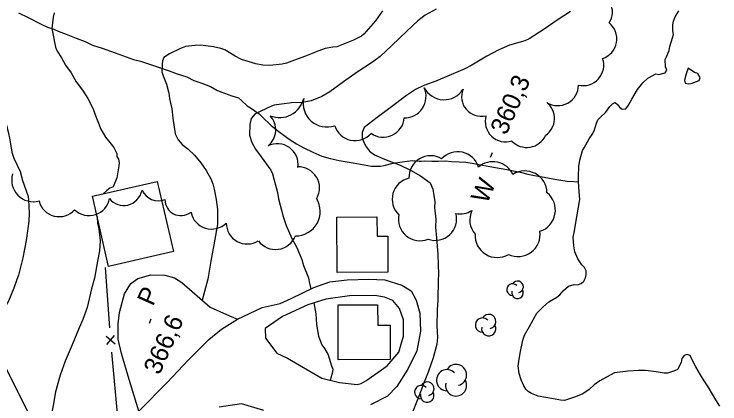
# Model space of a CAD drawing. Extents: x 287698 to 290158, y 5234163 to 5237182.
# Drawn here: x 288989.7 to 289106, y 5234678.1 to 5234742.3 of the extents above; entities that cross this region are included whole.
import ezdxf

# ---------------------------------------------------------------- set-up
doc = ezdxf.new("R2010")
doc.units = 0
for name, color, linetype in [('Niveau 1', 7, 'Continuous'), ('Niveau 19', 7, 'Continuous'), ('Niveau 2', 7, 'Continuous'), ('Niveau 3', 7, 'Continuous'), ('Niveau 31', 7, 'Continuous'), ('Niveau 37', 7, 'Continuous'), ('Niveau 4', 7, 'Continuous'), ('Niveau 44', 7, 'Continuous'), ('Niveau 52', 7, 'Continuous')]:
    doc.layers.add(name, color=color, linetype=linetype)

msp = doc.modelspace()

# ---------------------------------------------------------------- linework, layer by layer
at = {"layer": 'Niveau 1'}
for points in [[(288980.01, 5234742.77), (288979.81, 5234741.62), (288979.28, 5234738.63), (288979.42, 5234737.59), (288979.65, 5234737.06), (288980.74, 5234734.7), (288981.43, 5234733.68), (288982.27, 5234732.9), (288983.04, 5234731.98), (288984.94, 5234729.61), (288985.58, 5234728.54), (288986.45, 5234727.58), (288987.25, 5234726.58), (288987.91, 5234725.41), (288988.36, 5234724.15), (288988.68, 5234722.86), (288988.94, 5234721.55), (288989.28, 5234719.56), (288989.61, 5234718.55), (288990.18, 5234717.39), (288990.64, 5234716.36), (288990.95, 5234715.33), (288990.98, 5234715.04)], [(288990.98, 5234715.04), (288991.97, 5234712.23), (288992.01, 5234711.69), (288992.11, 5234709.46), (288992.06, 5234708.15), (288991.88, 5234706.55), (288991.62, 5234704.99), (288991.1, 5234702.12), (288990.39, 5234699.28), (288990.1, 5234698.54), (288989.6, 5234697.11), (288988.72, 5234694.99), (288987.99, 5234693.73), (288987.29, 5234692.27), (288986.15, 5234690.16), (288985.28, 5234688.81), (288984.18, 5234687.18)]]:
    msp.add_lwpolyline(points, dxfattribs=at)
at = {"layer": 'Niveau 19'}
for points in [[(289026.5, 5234692.01), (289030.59, 5234693.91), (289033.52, 5234694.59), (289035.37, 5234695.44), (289039.08, 5234697.25), (289041.74, 5234698.18), (289044.56, 5234698.49), (289048.15, 5234698.59), (289050.77, 5234698.47), (289053.6, 5234697.61), (289055.11, 5234696.69), (289055.97, 5234695.12), (289056.55, 5234693.01), (289056.66, 5234690.06), (289056.08, 5234686.77), (289054.57, 5234683.75), (289052.8, 5234680.94), (289051.21, 5234679.31), (289048.41, 5234677.91)], [(289047.68, 5234681.84), (289051.18, 5234684.33), (289053.1, 5234686.57), (289053.89, 5234689.19), (289053.85, 5234691.88), (289053.19, 5234693.76), (289052.1, 5234695.09), (289050.74, 5234695.64), (289049.12, 5234695.92), (289044.97, 5234695.86), (289041.08, 5234695.33), (289038.08, 5234694.35), (289033.93, 5234692.47), (289031.04, 5234690.46), (289031.11, 5234688.9), (289033, 5234686.4), (289034.75, 5234685.58), (289040.43, 5234682.3), (289043.3, 5234681.57), (289046.21, 5234681.24), (289046.91, 5234681.39), (289047.68, 5234681.84)], [(289010.22, 5234676.83), (289014.91, 5234681.58), (289018.41, 5234685.29), (289021.77, 5234688.66), (289023.87, 5234690.36), (289026.5, 5234692.01)], [(289030.84, 5234676.99), (289027.17, 5234678.06), (289023.48, 5234677.52)]]:
    msp.add_lwpolyline(points, dxfattribs=at)
at = {"layer": 'Niveau 2'}
for points in [[(289059.28, 5234743.09), (289057.43, 5234742.11), (289056.21, 5234741.2), (289054.46, 5234739.5), (289051.95, 5234737.09), (289050.01, 5234735.3), (289048.75, 5234734.38), (289046.22, 5234732.7), (289043.96, 5234731.12), (289041.74, 5234729.5), (289040.38, 5234728.71), (289038.67, 5234727.99), (289037.16, 5234727.74), (289035.38, 5234727.68), (289032.54, 5234727.3), (289032.11, 5234727.11), (289029.43, 5234725.87), (289028.74, 5234725.09), (289028.54, 5234724.07), (289028.47, 5234722.34), (289028.87, 5234721.13), (289029.47, 5234720.05), (289030.42, 5234718.79), (289032.02, 5234716.58), (289032.29, 5234715.98), (289033.07, 5234712.91), (289033.25, 5234711.82), (289034.02, 5234708.94), (289034.51, 5234707.47), (289035.43, 5234705.3), (289036.21, 5234703.93), (289037.11, 5234701.83), (289037.38, 5234700.87), (289038.2, 5234698.84), (289038.32, 5234698.16), (289038.59, 5234697.01)], [(288996.24, 5234742.47), (288996.11, 5234741.78), (288995.9, 5234739.89), (288996.03, 5234739.1), (288996.48, 5234736.84), (288996.78, 5234736.2), (288997.45, 5234735.09), (288998.11, 5234733.88), (288999.04, 5234732.59), (288999.9, 5234731.1), (289000.94, 5234729.74), (289001.83, 5234728.37), (289002.67, 5234726.69), (289002.99, 5234725.83), (289003.97, 5234723.32), (289004.73, 5234721.99), (289005.43, 5234721.13), (289006.11, 5234720.28), (289006.59, 5234719.32), (289006.6, 5234718.81), (289006.87, 5234718.36), (289006.99, 5234717.77), (289006.92, 5234717.27), (289006.57, 5234715.3), (289005.99, 5234713.82), (289005.44, 5234713.59), (289004.97, 5234713.23), (289004.35, 5234712.67)], [(289050.42, 5234742.81), (289049.24, 5234741.2), (289047.33, 5234738.97), (289046.93, 5234738.66), (289045.65, 5234737.98)], [(289081.44, 5234742.73), (289079.24, 5234741.29), (289077.05, 5234739.8), (289074.58, 5234738.19), (289073.88, 5234737.9), (289071.33, 5234737.15), (289069.47, 5234736.36), (289067.61, 5234735.36), (289065.13, 5234733.85), (289063.86, 5234733.19), (289061.79, 5234732.34), (289059.21, 5234731.25), (289057.2, 5234730.54), (289055.86, 5234729.86), (289054.38, 5234728.85), (289051.68, 5234726.84), (289049.55, 5234725.24), (289047.36, 5234723.6), (289047.04, 5234722.8), (289047.08, 5234721.81), (289047.59, 5234720.57), (289048.24, 5234719.69), (289049.11, 5234719.09), (289050.75, 5234718.4), (289053.31, 5234717.37), (289055.01, 5234716.58), (289056.67, 5234715.66), (289058.25, 5234714.46), (289058.7, 5234713.42), (289059.04, 5234711.35), (289059, 5234710.4), (289059.22, 5234708.5), (289059.17, 5234707.15), (289059.31, 5234705.42), (289059.56, 5234702.67), (289059.67, 5234699.4), (289059.58, 5234698.52), (289059.52, 5234695.13), (289059.41, 5234693.54), (289059.39, 5234690.92), (289059.48, 5234688.99), (289059.37, 5234687.88), (289058.77, 5234685.66), (289057.96, 5234683.26), (289057.27, 5234681.61), (289056.25, 5234678.88), (289055.18, 5234676.25)], [(289045.65, 5234737.98), (289042.89, 5234736.87), (289042.21, 5234736.81), (289040.96, 5234736.61), (289039.91, 5234736.22), (289037.7, 5234735.33), (289036.35, 5234734.88), (289034.6, 5234734.21), (289033.87, 5234734.06), (289031.83, 5234733.81), (289030.68, 5234733.87), (289029.5, 5234734.08), (289027.13, 5234734.78), (289026.13, 5234735.34), (289024.42, 5234736.37), (289023.76, 5234736.63), (289022.56, 5234736.87), (289020.42, 5234737.14), (289019.54, 5234737.13), (289017.9, 5234736.92), (289017.11, 5234736.59), (289015.3, 5234735.75), (289014.36, 5234735.16), (289014.15, 5234734.57), (289014.07, 5234734), (289014.02, 5234732.75), (289014.23, 5234732.1), (289014.76, 5234730.75), (289015.15, 5234729.26), (289015.27, 5234728.36), (289015.64, 5234726.65), (289015.85, 5234725.15), (289016.24, 5234722.57), (289016.72, 5234721.59), (289017.38, 5234720.82), (289018.28, 5234720.07), (289019.43, 5234719.02), (289020.46, 5234717.8), (289021.35, 5234716.53), (289022.12, 5234715.15), (289022.44, 5234714.3), (289022.65, 5234713.43), (289023, 5234711.71), (289023.22, 5234710.1), (289023.22, 5234709.29), (289023.17, 5234707.61), (289023.02, 5234706.75), (289022.58, 5234704.27), (289022.11, 5234701.59), (289021.58, 5234698.61), (289020.65, 5234695.15)], [(289003.33, 5234708.91), (289003.39, 5234707.79)], [(289003.39, 5234707.79), (289003.61, 5234706.89), (289003.83, 5234704.91), (289003.71, 5234703.27), (289003.43, 5234701.58), (289002.9, 5234698.79), (289002.4, 5234697.03), (289001.68, 5234693.96), (289001, 5234691.94), (289000.4, 5234690.57), (288999.21, 5234687.8), (288998.05, 5234685.08), (288997.24, 5234682.76), (288996.49, 5234680.02), (288996.08, 5234677.78), (288995.58, 5234675.3), (288994.99, 5234672.51), (288994.42, 5234669.37), (288994.37, 5234668.33), (288994.09, 5234665.85), (288993.76, 5234664.9), (288992.79, 5234663.25), (288991.58, 5234661.16)], [(289039.1, 5234694.68), (289039.41, 5234692.87), (289039.52, 5234691.16), (289039.86, 5234689.19), (289040.39, 5234687.76), (289040.83, 5234687.19), (289041.43, 5234686.16)], [(289041.43, 5234686.16), (289041.99, 5234684.33), (289042.2, 5234683.79), (289042.09, 5234683.08), (289041.76, 5234681.96)]]:
    msp.add_lwpolyline(points, dxfattribs=at)
at = {"layer": 'Niveau 3'}
for p, q in [((289068.24, 5234718.73), (289068.56, 5234719.46)), ((289011.96, 5234691.33), (289012.28, 5234692.06))]:
    msp.add_line(p, q, dxfattribs=at)
at = {"layer": 'Niveau 31'}
for points in [[(289015.93, 5234703.19), (289005.21, 5234700.72), (289002.56, 5234712.26), (289013.27, 5234714.72)], [(289042.92, 5234699.73), (289042.88, 5234708.84), (289049.5, 5234708.87), (289049.51, 5234705.7), (289051.3, 5234705.71), (289051.31, 5234699.75)], [(289043.09, 5234685.34), (289043.07, 5234694.36), (289049.61, 5234694.37), (289049.62, 5234691), (289051.68, 5234691.01), (289051.69, 5234685.35)], [(288986.97, 5234686.52), (288992.02, 5234676.45), (288980.83, 5234670.83), (288975.78, 5234680.9)]]:
    msp.add_lwpolyline(points, close=True, dxfattribs=at)
at = {"layer": 'Niveau 37'}
for p, q in [((289004.67, 5234700.54), (289005.41, 5234690.58)), ((289004.81, 5234689.23), (289006.34, 5234687.93)), ((289004.93, 5234687.82), (289006.23, 5234689.35)), ((289005.74, 5234686.59), (289006.85, 5234674.3))]:
    msp.add_line(p, q, dxfattribs=at)
at = {"layer": 'Niveau 4'}
for points in [[(288990.38, 5234742.48), (288991.95, 5234741.71), (288994.09, 5234740.61), (288995.18, 5234740.13), (288996.18, 5234739.79), (288996.93, 5234739.46), (288998.25, 5234738.98), (288999.9, 5234738.32), (289001.35, 5234737.78), (289002.6, 5234737.18), (289004.17, 5234736.65), (289006.33, 5234735.89), (289008.11, 5234735.25), (289009.33, 5234734.79), (289010.5, 5234734.52), (289011.65, 5234734.12), (289013.49, 5234733.53), (289015.24, 5234732.94), (289016.53, 5234732.43), (289018.12, 5234731.92), (289019.29, 5234731.37), (289020.61, 5234730.91), (289022.05, 5234730.33), (289023.1, 5234729.74), (289023.72, 5234729.45), (289025.56, 5234728.84), (289026.66, 5234728.49), (289027.17, 5234728.07), (289028.09, 5234727.18), (289028.64, 5234726.84), (289030.05, 5234725.84), (289030.55, 5234725.34), (289032.05, 5234723.92), (289033.1, 5234723.09), (289035, 5234721.67), (289036.25, 5234720.91), (289037.45, 5234720.27), (289038.93, 5234719.56), (289040.38, 5234718.9), (289041.77, 5234718.47), (289043.28, 5234718.18), (289045.55, 5234717.78), (289046.79, 5234717.56), (289048.58, 5234717.25), (289050.1, 5234717.22), (289050.69, 5234717.36), (289052.19, 5234717.71), (289053.64, 5234717.96), (289055.29, 5234718.14), (289056.46, 5234718.05), (289056.86, 5234718.04), (289057.34, 5234718.12), (289058.53, 5234718.05), (289059.65, 5234718.06), (289060.76, 5234718.13), (289061.81, 5234717.98), (289063.06, 5234717.96), (289064.13, 5234717.9), (289065.19, 5234717.71), (289066.31, 5234717.51), (289068.13, 5234717.19), (289070.9, 5234716.7), (289073.14, 5234716.25), (289074.39, 5234715.89), (289075.48, 5234715.69), (289077.7, 5234715.3), (289078.81, 5234715.11), (289079.81, 5234714.93), (289080.89, 5234714.74), (289081.95, 5234714.72), (289082.76, 5234714.66), (289082.76, 5234714.66)], [(289095.48, 5234732.42), (289095.99, 5234732.33), (289097.05, 5234732.59), (289097.32, 5234733.07), (289097.07, 5234733.62), (289097, 5234734.81), (289097.26, 5234735.24), (289097.71, 5234736.29), (289097.82, 5234736.94), (289098.24, 5234738.39), (289098.39, 5234738.93), (289098.31, 5234739.5), (289098.27, 5234740.54), (289098.38, 5234741.13), (289098.66, 5234741.83), (289099.26, 5234742.82)], [(289100.83, 5234733.4), (289100.51, 5234732.42), (289100.23, 5234731.41), (289100.31, 5234730.91), (289100.81, 5234730.78), (289101.31, 5234730.83), (289102.64, 5234731.33), (289102.8, 5234731.81), (289102.39, 5234732.47), (289101.87, 5234732.66), (289100.83, 5234733.4)], [(289082.76, 5234714.66), (289082.71, 5234715.54), (289082.8, 5234717.17), (289082.98, 5234718.22), (289083.37, 5234719.81), (289083.65, 5234720.25), (289084.47, 5234721.71), (289085.12, 5234722.61), (289085.35, 5234723.22), (289085.68, 5234724.32), (289085.94, 5234724.84), (289086.31, 5234725.24), (289087.24, 5234726.14), (289087.89, 5234727.06), (289088.32, 5234727.51), (289088.8, 5234727.73), (289089.17, 5234727.38), (289089.48, 5234726.96), (289089.93, 5234726.62), (289090.55, 5234726.69), (289090.96, 5234727.29), (289091.52, 5234728.27), (289092.47, 5234729.84), (289093.35, 5234730.95), (289094.14, 5234731.74), (289095.48, 5234732.42)], [(289106.05, 5234677.67), (289105.39, 5234678.74), (289104.14, 5234680.87), (289103.46, 5234681.85), (289102.88, 5234682.84), (289102.06, 5234684.17), (289101.39, 5234685.56), (289101.13, 5234686.03), (289100.65, 5234686.2), (289100.16, 5234686.04), (289099.79, 5234685.56), (289099.67, 5234684.89), (289099.04, 5234683.74), (289098.58, 5234683.52), (289097.39, 5234683.12), (289096.86, 5234683.13), (289095.56, 5234683.36), (289093.77, 5234683.56), (289092.65, 5234683.55), (289090.92, 5234683.43), (289088.66, 5234683.16), (289087.95, 5234682.81), (289086.24, 5234681.86), (289085.33, 5234681.19), (289084.5, 5234680.4), (289083.47, 5234679.73), (289082.26, 5234679.21), (289080.4, 5234678.6), (289079.79, 5234678.67), (289078.59, 5234678.88), (289076.1, 5234679.32), (289074.98, 5234679.76), (289074.42, 5234680.12), (289074.06, 5234680.49), (289073.69, 5234681.04), (289073.27, 5234682.01), (289072.95, 5234683.06), (289072.78, 5234684.29), (289072.87, 5234685.03), (289073.11, 5234686.41), (289073.53, 5234688.57), (289073.85, 5234689.36), (289074.64, 5234690.81), (289075.88, 5234693.03), (289076.87, 5234694.01), (289077.85, 5234694.89), (289079.14, 5234695.62), (289079.65, 5234696), (289080.22, 5234696.67), (289081.09, 5234697.45), (289082.03, 5234697.71), (289082.55, 5234697.68), (289083.18, 5234697.91), (289083.63, 5234698.28), (289083.91, 5234698.82), (289084.01, 5234699.39), (289083.97, 5234699.99), (289083.74, 5234700.51), (289083.31, 5234700.96), (289082.61, 5234701.93), (289082.11, 5234703.12), (289081.96, 5234704.1), (289081.86, 5234705.54), (289082, 5234706.29), (289082.51, 5234709.22), (289082.96, 5234711.76), (289082.86, 5234713.02), (289082.76, 5234714.66)]]:
    msp.add_lwpolyline(points, dxfattribs=at)
at = {"layer": 'Niveau 44'}
for centre, radius, start, end in [((289071.86, 5234696.87), 0.957, 44.1154, 269.804), ((289072.68, 5234697.34), 0.957, 282.2692, 149.7263), ((289072.68, 5234696.39), 0.957, 166.9369, 29.6212), ((289066.91, 5234691.04), 1.18, 44.1154, 269.804), ((289067.93, 5234691.63), 1.18, 282.2692, 149.7263), ((289067.93, 5234690.45), 1.18, 166.9369, 29.6212), ((289061.06, 5234681.96), 1.74, 44.1154, 269.804), ((289062.55, 5234682.83), 1.74, 282.2692, 149.7263), ((289057.79, 5234680.55), 1.12, 282.2692, 149.7263), ((289062.55, 5234681.09), 1.74, 166.9369, 29.6212), ((289056.83, 5234679.99), 1.12, 44.1154, 269.804), ((289057.79, 5234679.43), 1.12, 166.9369, 29.6212)]:
    msp.add_arc(centre, radius, start, end, dxfattribs=at)
for centre, major_axis, ratio, start_param, end_param in [((289084.97, 5234742.53), (3.23, 0.99), 0.946871, 5.417944, 7.568909), ((289085.68, 5234738.19), (2.07, 2.67), 0.996208, 4.117522, 6.271324), ((289083.56, 5234733.84), (2.26, 2.5), 0.984701, 3.633612, 5.791166), ((289054.22, 5234728.62), (1.88, 2.9), 0.966204, 3.668324, 5.73219), ((289060.57, 5234731.88), (-0.27, -3.7), 0.999981, 5.274301, 7.350946), ((289079.37, 5234730.53), (2.97, 1.62), 0.976831, 3.635787, 5.788991), ((289066.82, 5234728.69), (-3.27, -0.83), 0.957028, 5.643272, 7.801193), ((289033.43, 5234729.35), (1, -3.99), 0.997275, 5.657153, 7.373276), ((289041.35, 5234727.71), (-2.72, -3.06), 0.965665, 5.252607, 7.324973), ((289075.41, 5234725.09), (-0.72, 3.3), 0.996472, 3.520301, 5.396916), ((289029.39, 5234723.23), (3.36, 0.58), 0.999437, 5.222143, 6.852609), ((289070.71, 5234724.58), (2.42, -2.35), 0.991599, 3.634098, 5.79068), ((289050.58, 5234725.4), (2.95, 1.8), 0.979171, 3.530809, 5.669148), ((289045.88, 5234724.96), (-0.81, -3.43), 0.99627, 5.24915, 7.364773), ((289074.23, 5234723.63), (3.27, 0.85), 0.979388, 3.632744, 5.606534), ((289033.05, 5234717.49), (-2.8, 2.01), 0.999864, 3.631568, 5.79321), ((289062.81, 5234716.05), (-0.42, 3.54), 0.999629, 4.877923, 7.003391), ((289058.32, 5234715.39), (-1.32, 3.3), 0.999706, 5.357475, 7.515802), ((289068.63, 5234714.3), (0.65, 3.6), 0.997834, 5.333222, 7.181659), ((289036.59, 5234713.67), (-2.2, 2.67), 0.989706, 3.48698, 5.638242), ((289073.89, 5234712.79), (0.29, 3.64), 0.998001, 4.806502, 6.931137), ((288992.83, 5234714.94), (-2.98, -1.98), 0.999893, 5.40671, 7.533436), ((289055.55, 5234711.78), (-0.95, -3.42), 0.999943, 3.631685, 5.793093), ((289007.76, 5234714.17), (-0.29, -3.44), 0.90577, 5.510808, 7.668068), ((289013.61, 5234714.96), (-1.07, -3.29), 0.90577, 5.510808, 6.919354), ((289075.26, 5234709.98), (0.68, 3.6), 0.998901, 3.636573, 5.788205), ((288997.11, 5234712.34), (2.72, 2.14), 0.988187, 2.719499, 4.871863), ((289001.98, 5234712.49), (3.3, -1.03), 0.980984, 4.258883, 6.414706), ((289017.61, 5234712.39), (-1.97, -2.84), 0.840096, 5.439397, 7.375856), ((289036.08, 5234709.79), (3.4, -2.22), 0.999273, 5.280723, 7.407739), ((289022.21, 5234710.3), (3.14, -1.44), 0.996313, 3.771783, 5.922043), ((289056.59, 5234708.5), (2.74, -2.27), 0.999871, 3.635459, 5.789319), ((289059.08, 5234708.55), (-0.71, 3.48), 0.999859, 2.607039, 4.764983), ((289063.25, 5234712.93), (2.3, 2.71), 0.999943, 3.635522, 4.405757), ((289068.45, 5234708.39), (-0.06, -3.65), 0.998984, 4.2977, 5.437416), ((289028.12, 5234707.9), (-1.7, -3.07), 0.988866, 5.227891, 7.33909), ((289032.76, 5234707.03), (0.46, -3.5), 0.999574, 5.22292, 7.346694), ((289069.32, 5234705.82), (3.12, -1.89), 0.999343, 3.631273, 5.793505), ((289072.76, 5234705.98), (0.93, 3.53), 0.99865, 2.952892, 5.113649)]:
    msp.add_ellipse(centre, major_axis=major_axis, ratio=ratio, start_param=start_param, end_param=end_param, dxfattribs=at)
at = {"layer": 'Niveau 52'}
msp.add_lwpolyline([(289010.22, 5234676.83), (289008.45, 5234682.6), (289007.39, 5234686.38), (289006.81, 5234688.7), (289006.83, 5234691.25), (289007.04, 5234693.13), (289007.87, 5234696.21), (289008.91, 5234697.87), (289010.08, 5234698.74), (289012.21, 5234699.32), (289014.52, 5234699.28), (289016.1, 5234698.8), (289017.33, 5234698.07), (289021.97, 5234693.99), (289025.16, 5234692.59), (289026.5, 5234692.01)], dxfattribs=at)

# ---------------------------------------------------------------- texts
at = {"layer": 'Niveau 3'}
for s, p in [('360,3', (289070.8, 5234722.2)), ('366,6', (289013.62, 5234682.69))]:
    msp.add_text(s, height=3, rotation=66.1217, dxfattribs=at).set_placement(p)
at = {"layer": 'Niveau 44'}
msp.add_text('W', height=3, rotation=66.1217, dxfattribs=at).set_placement((289067.63, 5234710.88))
at = {"layer": 'Niveau 52'}
msp.add_text('P', height=3, rotation=66.1217, dxfattribs=at).set_placement((289012.57, 5234694.03))

doc.saveas('drawing.dxf')
